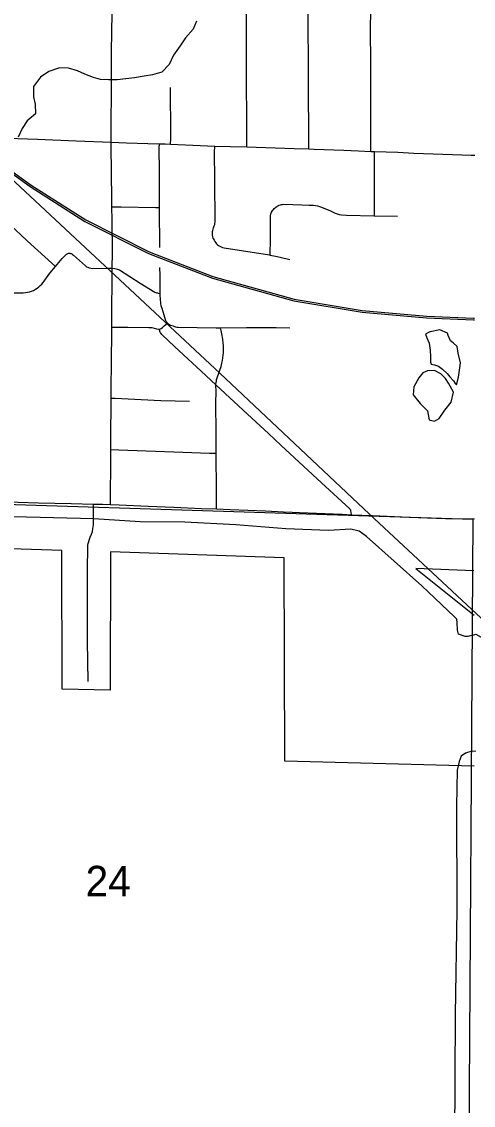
# Model space of a CAD drawing. Extents: x 0 to 34, y 0 to 22.
# Drawn here: x 4.081 to 4.702, y 16.541 to 18.031 of the extents above; entities that cross this region are included whole.
import ezdxf

# ---------------------------------------------------------------- set-up
doc = ezdxf.new("R2010")
doc.units = 0
for name, color, linetype in [('GM_X_City_Street', 7, 'Continuous'), ('GM_X_Corporation', 7, 'Continuous'), ('GM_X_Minor_Lake', 7, 'Continuous'), ('GM_X_Minor_River', 7, 'Continuous'), ('GM_X_Rail_Line', 7, 'Continuous'), ('GM_X_Section', 7, 'Continuous'), ('GM_X_Section_Text', 7, 'Continuous'), ('GM_X_State_Route', 7, 'Continuous'), ('GM_X_Township_Road', 7, 'Continuous')]:
    doc.layers.add(name, color=color, linetype=linetype)

msp = doc.modelspace()

# ---------------------------------------------------------------- linework, layer by layer
at = {"layer": 'GM_X_City_Street'}
for points in [[(4.4761, 17.8564), (4.4762, 17.8627), (4.476, 17.8834), (4.4758, 17.9298), (4.4758, 17.9786), (4.4753, 18.0223), (4.4755, 18.0881), (4.4756, 18.0908), (4.4757, 18.0928), (4.4758, 18.0944), (4.4761, 18.0959), (4.4764, 18.0969), (4.4769, 18.0978), (4.4774, 18.0985), (4.4778, 18.099), (4.4782, 18.0994)], [(4.5613, 17.853), (4.5613, 17.859), (4.5615, 17.894), (4.5613, 17.9791), (4.5612, 18.0155), (4.5616, 18.0522), (4.5617, 18.0818), (4.5616, 18.0855), (4.5615, 18.0892), (4.5611, 18.0916), (4.5607, 18.0941), (4.5603, 18.0961), (4.5599, 18.0976), (4.5592, 18.0993)], [(4.2034, 17.3675), (4.2033, 17.3746), (4.2039, 17.4281), (4.204, 17.4432), (4.204, 17.4585), (4.2044, 17.5106), (4.2044, 17.5138), (4.2044, 17.5249), (4.2052, 17.6038), (4.2053, 17.6114), (4.2054, 17.6261), (4.2058, 17.6845), (4.2059, 17.6922), (4.206, 17.714), (4.2058, 17.7584), (4.2054, 17.7769), (4.2052, 17.7872), (4.2044, 17.8603), (4.2045, 17.8656), (4.2045, 17.8958), (4.2047, 17.9299), (4.2047, 17.9591), (4.2047, 17.9902), (4.2056, 18.043)], [(4.2861, 17.8631), (4.2862, 17.87), (4.2863, 17.8793), (4.2861, 17.9371), (4.2861, 17.9408)], [(4.062, 17.8713), (4.0893, 17.87), (4.1028, 17.8696), (4.1561, 17.8674), (4.2045, 17.8656), (4.2256, 17.8648), (4.2546, 17.864), (4.2706, 17.8635), (4.2784, 17.8633), (4.2861, 17.8631), (4.3167, 17.8615), (4.3468, 17.86), (4.3678, 17.8595), (4.3909, 17.8591), (4.456, 17.8568), (4.4761, 17.8564), (4.4835, 17.8561), (4.5242, 17.8546), (4.5447, 17.8537), (4.5613, 17.853), (4.5666, 17.8527), (4.5986, 17.8517), (4.6207, 17.8505), (4.6738, 17.8485), (4.6993, 17.8479), (4.7044, 17.8478)], [(4.2711, 17.7208), (4.2707, 17.7748), (4.2707, 17.7758), (4.2707, 17.8256), (4.2705, 17.8573), (4.2706, 17.8635)], [(4.3447, 17.7334), (4.344, 17.736), (4.3437, 17.738), (4.3436, 17.7396), (4.3436, 17.7412), (4.3437, 17.7428), (4.344, 17.7443), (4.3453, 17.748), (4.3462, 17.7506), (4.3468, 17.7524), (4.3471, 17.7538), (4.3472, 17.7557), (4.3468, 17.8144), (4.3467, 17.852), (4.3468, 17.86)], [(4.5667, 17.7645), (4.5666, 17.7719), (4.5665, 17.788), (4.5666, 17.8438), (4.5666, 17.8527)], [(4.2054, 17.7769), (4.2179, 17.7767), (4.2654, 17.7759), (4.2707, 17.7758)], [(4.4232, 17.7105), (4.4232, 17.715), (4.4233, 17.7284), (4.4233, 17.7602), (4.4234, 17.7626), (4.4235, 17.7646), (4.4239, 17.7666), (4.4243, 17.7679), (4.425, 17.7694), (4.4256, 17.7707), (4.4265, 17.772), (4.4275, 17.7732), (4.4285, 17.7743), (4.4297, 17.7754), (4.4308, 17.7763), (4.4322, 17.7773), (4.4338, 17.7782), (4.4355, 17.779), (4.4371, 17.7795), (4.4385, 17.7798), (4.4401, 17.7801), (4.442, 17.7802), (4.4664, 17.7795), (4.4767, 17.7792), (4.4826, 17.7788), (4.4855, 17.7784), (4.4883, 17.7779), (4.4909, 17.7772), (4.4937, 17.7762), (4.4967, 17.7751), (4.5003, 17.7735), (4.506, 17.771), (4.5095, 17.7693), (4.5125, 17.7681), (4.5153, 17.7671), (4.5181, 17.7663), (4.5211, 17.7659), (4.5279, 17.7654), (4.566, 17.7645), (4.5667, 17.7645), (4.5982, 17.7637)], [(4.1276, 17.6949), (4.0888, 17.7299), (4.0645, 17.7528)], [(4.3447, 17.7334), (4.3458, 17.731), (4.3469, 17.729), (4.3481, 17.7274), (4.3493, 17.726), (4.3507, 17.7247), (4.3522, 17.7235), (4.3538, 17.7226), (4.3557, 17.7216), (4.3575, 17.7209), (4.3597, 17.7203), (4.422, 17.7107), (4.4232, 17.7105), (4.4306, 17.7091), (4.4366, 17.7077), (4.45, 17.7045)], [(4.047, 17.6587), (4.0834, 17.6586), (4.0865, 17.6588), (4.0892, 17.6592), (4.0919, 17.6598), (4.0947, 17.6607), (4.0976, 17.6619), (4.1003, 17.6634), (4.1026, 17.6649), (4.1048, 17.6666), (4.1069, 17.6684), (4.109, 17.6706), (4.1108, 17.6728), (4.1199, 17.6854), (4.1276, 17.6949), (4.1369, 17.7055), (4.1426, 17.7112), (4.1434, 17.7118), (4.144, 17.7123), (4.1449, 17.7126), (4.1458, 17.7129), (4.1468, 17.713), (4.1477, 17.7129), (4.1486, 17.7127), (4.1495, 17.7124), (4.1504, 17.7119), (4.1513, 17.7114), (4.1524, 17.7104), (4.1689, 17.6955), (4.1705, 17.6943), (4.1721, 17.6936), (4.174, 17.6929), (4.1762, 17.6924), (4.1793, 17.6921), (4.1988, 17.6922), (4.2059, 17.6922)], [(4.2059, 17.6922), (4.2094, 17.6919), (4.2114, 17.6916), (4.2131, 17.6912), (4.2144, 17.6906), (4.2157, 17.69), (4.2443, 17.672), (4.2645, 17.6596), (4.2656, 17.6591), (4.2667, 17.6586), (4.2679, 17.6583), (4.269, 17.658), (4.2716, 17.6577)], [(4.2817, 17.617), (4.2813, 17.6175), (4.2804, 17.6185), (4.2799, 17.6191), (4.2794, 17.6202), (4.2772, 17.6276), (4.2743, 17.637), (4.2733, 17.6406), (4.2727, 17.6442), (4.2717, 17.6554), (4.2716, 17.6577), (4.2716, 17.6694), (4.2717, 17.6828), (4.2715, 17.6931)], [(4.2053, 17.6114), (4.2104, 17.6114), (4.2272, 17.6113), (4.2563, 17.6109), (4.2586, 17.6108), (4.2605, 17.6107), (4.2634, 17.6101), (4.2669, 17.6091), (4.2695, 17.6085), (4.2708, 17.6085), (4.2721, 17.6088), (4.2732, 17.6093), (4.2748, 17.6108), (4.2774, 17.6133), (4.2817, 17.617), (4.2834, 17.6159), (4.2846, 17.6151), (4.2861, 17.6142), (4.2877, 17.6135), (4.2894, 17.6129), (4.2913, 17.6122), (4.293, 17.6118), (4.2946, 17.6115), (4.2963, 17.6113), (4.3486, 17.6104), (4.3547, 17.6105), (4.3906, 17.6107), (4.4168, 17.6109), (4.4311, 17.6109), (4.4501, 17.6105)], [(4.5349, 17.3534), (4.5344, 17.357), (4.5342, 17.3586), (4.5338, 17.3598), (4.5332, 17.3607), (4.5325, 17.3616), (4.4937, 17.3971), (4.4564, 17.4315), (4.4382, 17.4485), (4.4206, 17.465), (4.3976, 17.4863), (4.3612, 17.52), (4.3485, 17.5318), (4.328, 17.5509), (4.3039, 17.5733), (4.2916, 17.5847), (4.283, 17.5927), (4.2741, 17.6012), (4.2725, 17.603), (4.2719, 17.604), (4.2715, 17.6051), (4.2712, 17.6062), (4.271, 17.6074), (4.2708, 17.6085)], [(4.3494, 17.3616), (4.3493, 17.3694), (4.3491, 17.3982), (4.3489, 17.4256), (4.3488, 17.438), (4.3488, 17.4666), (4.3485, 17.5067), (4.3486, 17.5227), (4.3485, 17.5318), (4.3488, 17.5358), (4.349, 17.5371), (4.3493, 17.5388), (4.3539, 17.552), (4.3555, 17.5574), (4.3565, 17.5616), (4.3573, 17.5655), (4.3578, 17.5689), (4.3583, 17.5728), (4.3587, 17.5766), (4.3589, 17.5802), (4.359, 17.5832), (4.3588, 17.5863), (4.3585, 17.5892), (4.3579, 17.5948), (4.3567, 17.6021), (4.3555, 17.6069), (4.3547, 17.6105)], [(4.2044, 17.5138), (4.2099, 17.5135), (4.2727, 17.5106), (4.312, 17.5095)], [(4.204, 17.4432), (4.2148, 17.4428), (4.303, 17.4392), (4.3396, 17.4382), (4.3488, 17.438)], [(4.1725, 17.1241), (4.172, 17.1794), (4.1717, 17.2389), (4.1716, 17.2781), (4.1722, 17.309), (4.1724, 17.3115), (4.1727, 17.3139), (4.1735, 17.3166), (4.1744, 17.3196), (4.1755, 17.3226), (4.1772, 17.3266), (4.1786, 17.3305), (4.1793, 17.3338), (4.1797, 17.3367), (4.18, 17.3396), (4.1799, 17.3586), (4.1799, 17.3681)]]:
    msp.add_lwpolyline(points, dxfattribs=at)
at = {"layer": 'GM_X_Corporation'}
for points in [[(4.7035, 17.0079), (4.4431, 17.0144), (4.4423, 17.294), (4.2034, 17.3023), (4.2031, 17.1122), (4.1368, 17.1138), (4.1367, 17.3044), (3.7029, 17.3184), (3.7023, 17.3641), (3.7022, 17.3816), (3.7013, 17.6306), (3.7003, 17.7209), (3.7005, 17.7576), (3.7011, 17.8859), (3.7017, 18.3895)], [(4.7033, 17.2765), (4.6234, 17.2793), (4.7035, 17.2155)]]:
    msp.add_lwpolyline(points, dxfattribs=at)
at = {"layer": 'GM_X_Minor_Lake'}
for p, q in [((4.6416, 17.5893), (4.6431, 17.5798)), ((4.6277, 17.5415), (4.6208, 17.5294))]:
    msp.add_line(p, q, dxfattribs=at)
for points in [[(4.6431, 17.5798), (4.6434, 17.5707), (4.6437, 17.5631), (4.6445, 17.5604), (4.649, 17.5596), (4.6547, 17.5577), (4.6599, 17.5535), (4.6663, 17.5477), (4.6701, 17.5432), (4.6753, 17.5374), (4.6776, 17.534), (4.6795, 17.5321), (4.6822, 17.5427), (4.6841, 17.5556), (4.6849, 17.5624), (4.6816, 17.5757), (4.6802, 17.5845), (4.6749, 17.5898), (4.6712, 17.5925), (4.6678, 17.5997), (4.6671, 17.6031), (4.6565, 17.6074), (4.6429, 17.6048), (4.6417, 17.6044), (4.6368, 17.6018), (4.6383, 17.5965), (4.6416, 17.5893)], [(4.6208, 17.5294), (4.6196, 17.5181), (4.6294, 17.5062), (4.6395, 17.4963), (4.6417, 17.4841), (4.6492, 17.4822), (4.6553, 17.4856), (4.6633, 17.4973), (4.6721, 17.5082), (4.6752, 17.5219), (4.6681, 17.5344), (4.6644, 17.5409), (4.658, 17.547), (4.6489, 17.5516), (4.6395, 17.5513), (4.633, 17.5483), (4.6277, 17.5415)]]:
    msp.add_lwpolyline(points, dxfattribs=at)
at = {"layer": 'GM_X_Minor_River'}
for points in [[(4.3219, 18.0322), (4.3172, 18.0209), (4.3068, 18.0093), (4.2991, 17.998), (4.2902, 17.9853), (4.2843, 17.9724), (4.2739, 17.962), (4.2614, 17.9584), (4.2496, 17.9563), (4.2363, 17.9542), (4.2246, 17.9525), (4.2128, 17.9512), (4.2007, 17.9514), (4.1898, 17.952), (4.18, 17.9544), (4.1679, 17.9591), (4.1582, 17.9635), (4.1458, 17.9675), (4.1333, 17.9677), (4.1188, 17.963), (4.107, 17.9552), (4.0973, 17.9424), (4.0975, 17.928), (4.1, 17.9177), (4.1001, 17.9048), (4.0886, 17.8948), (4.082, 17.8846), (4.0765, 17.8726)], [(4.7016, 17.188), (4.6949, 17.1862), (4.6911, 17.1859), (4.6821, 17.1891), (4.6807, 17.1948), (4.6801, 17.2047), (4.6798, 17.21), (4.6768, 17.2131), (4.6317, 17.2556), (4.5556, 17.3236), (4.5455, 17.331), (4.5338, 17.3334), (4.5031, 17.3317), (4.4445, 17.3341), (4.3758, 17.3394), (4.3055, 17.3432), (4.2442, 17.3438), (4.1803, 17.3479), (4.0695, 17.3504)], [(4.7016, 17.188), (4.7058, 17.1894), (4.7345, 17.1731), (4.7648, 17.1562)], [(4.7006, 17.0285), (4.6915, 17.0258), (4.6859, 17.0213), (4.6828, 17.0141), (4.6803, 17.002), (4.6792, 16.9527), (4.6799, 16.81), (4.6773, 16.6662), (4.6768, 16.4928), (4.6751, 16.3793), (4.6751, 16.3346), (4.6764, 16.1979), (4.6763, 16.0257), (4.6763, 15.9088), (4.6786, 15.7672), (4.6786, 15.6466), (4.6794, 15.5312), (4.6803, 15.3255), (4.5472, 15.3266), (4.4349, 15.3284), (4.3256, 15.329), (4.2223, 15.3295), (4.0419, 15.3313), (3.8902, 15.3326)], [(4.7006, 17.0285), (4.706, 17.0289)]]:
    msp.add_lwpolyline(points, dxfattribs=at)
at = {"layer": 'GM_X_Rail_Line'}
for points in [[(2.1, 19.6439), (2.1012, 19.6428), (2.4982, 19.2743), (2.9696, 18.8359), (3.3468, 18.4857), (3.702, 18.1547), (3.9505, 17.921), (4.0191, 17.8627), (4.0357, 17.8486), (4.0945, 17.8067), (4.1695, 17.7587), (4.2566, 17.7148), (4.3444, 17.681), (4.4559, 17.6499), (4.5498, 17.6344), (4.6383, 17.6263), (4.7029, 17.6237), (4.7039, 17.6237)], [(2.1, 19.64), (2.4967, 19.2714), (2.9674, 18.8343), (3.3458, 18.483), (3.6997, 18.1544), (3.9489, 17.9193), (4.0176, 17.861), (4.0342, 17.8468), (4.0931, 17.8048), (4.1683, 17.7567), (4.2556, 17.7127), (4.3436, 17.6788), (4.4554, 17.6477), (4.5495, 17.6321), (4.6381, 17.624), (4.7029, 17.6214), (4.7039, 17.6214)], [(4.0173, 17.8615), (4.3536, 17.5482), (4.5597, 17.354), (4.6999, 17.2234)], [(4.6999, 17.2234), (5.1959, 16.7623), (5.6141, 16.3779), (6.1219, 15.9048), (6.7692, 15.2987), (7.1796, 14.9035), (7.6056, 14.5217)]]:
    msp.add_lwpolyline(points, dxfattribs=at)
at = {"layer": 'GM_X_Section'}
msp.add_lwpolyline([(4.6959, 16.4195), (4.6953, 16.3562), (3.7046, 16.3661), (3.7003, 17.3796), (4.7018, 17.3475)], close=True, dxfattribs=at)
at = {"layer": 'GM_X_State_Route'}
for points in [[(3.7505, 17.38), (3.7659, 17.3796), (3.8134, 17.3781), (3.8544, 17.377), (3.9292, 17.375), (3.9839, 17.3734), (4.0765, 17.3708), (4.1045, 17.3698), (4.1492, 17.369), (4.1799, 17.3681), (4.1924, 17.3678), (4.2034, 17.3675), (4.2153, 17.3669), (4.2552, 17.3652), (4.2904, 17.3638), (4.3285, 17.3621), (4.3494, 17.3616), (4.3678, 17.3608), (4.4164, 17.3587), (4.4415, 17.3575)], [(4.4415, 17.3575), (4.4534, 17.3569), (4.4635, 17.3564)], [(4.4635, 17.3564), (4.5221, 17.354), (4.5349, 17.3534), (4.5637, 17.3523), (4.614, 17.3501), (4.6641, 17.348), (4.7041, 17.3477)]]:
    msp.add_lwpolyline(points, dxfattribs=at)
at = {"layer": 'GM_X_Township_Road'}
msp.add_lwpolyline([(4.3909, 17.8591), (4.3908, 17.8662), (4.3908, 17.8994), (4.3905, 17.9465), (4.3906, 17.9913), (4.3905, 18.0377), (4.3904, 18.0556), (4.3903, 18.0859), (4.3901, 18.1062)], dxfattribs=at)

# ---------------------------------------------------------------- texts
at = {"layer": 'GM_X_Section_Text'}
msp.add_text('24', height=0.04186, rotation=0, dxfattribs=at).set_placement((4.1691, 16.8288))

doc.saveas('drawing.dxf')
